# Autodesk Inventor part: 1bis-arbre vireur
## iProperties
Created: 2011-02
Part Number: 1bis-arbre vireur
Document SubType Name: Modeling
Designer: eric
Density: 1 g/cm^3
Author: eric
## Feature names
1. Base1
